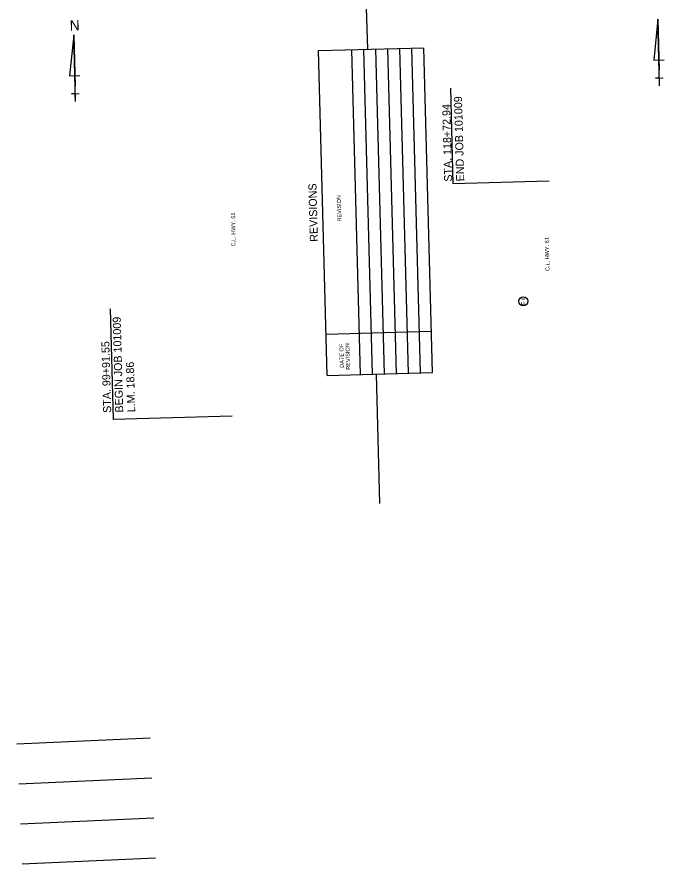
# Model space of a CAD drawing. Extents: x 1930579 to 1931599, y 596452 to 598574.
# Drawn here: x 1930579 to 1931549, y 596452 to 597722 of the extents above; entities that cross this region are included whole.
import ezdxf

# ---------------------------------------------------------------- set-up
doc = ezdxf.new("R2010")
doc.units = 0
for name, color, linetype in [('BR_Pr_Bent_CL', 7, 'Continuous'), ('Default', 7, 'Continuous'), ('R_Annotation', 7, 'Continuous'), ('R_Border', 7, 'Continuous'), ('R_Erosion', 7, 'Continuous'), ('S_BASELINE', 7, 'Continuous')]:
    doc.layers.add(name, color=color, linetype=linetype)

msp = doc.modelspace()

# ---------------------------------------------------------------- linework, layer by layer
at = {"layer": 'BR_Pr_Bent_CL'}
for p, q in [((1930779.3, 596640.3), (1930579.5, 596631.6)), ((1930781.9, 596580.4), (1930582.1, 596571.7)), ((1930784.5, 596520.4), (1930584.7, 596511.8)), ((1930787.1, 596460.5), (1930587.3, 596451.8))]:
    msp.add_line(p, q, dxfattribs=at)
at = {"layer": 'R_Annotation'}
for points in [[(1931377.2, 597475.2), (1931233.5, 597471.3), (1931229.7, 597615)], [(1930901.9, 597122.9), (1930724, 597118.1), (1930719.5, 597283.8)]]:
    msp.add_lwpolyline(points, dxfattribs=at)
at = {"layer": 'R_Border'}
for p, q in [((1931105.2, 597673), (1931088, 598314)), ((1931540.1, 597718.4), (1931534, 597656.6)), ((1931542.8, 597618.4), (1931540.1, 597718.4)), ((1931540.1, 597718.4), (1931542.1, 597641.5)), ((1930664.6, 597694.9), (1930658.5, 597633.1)), ((1930667.3, 597594.9), (1930664.6, 597694.9)), ((1930664.6, 597694.9), (1930666.6, 597618)), ((1931534, 597656.6), (1931549.4, 597657)), ((1931542.8, 597618.4), (1931542.1, 597641.5)), ((1930658.5, 597633.1), (1930673.9, 597633.5)), ((1931536.7, 597629.8), (1931548.2, 597630.1)), ((1931542.4, 597629.9), (1931536.7, 597629.8)), ((1931542.8, 597618.4), (1931542.4, 597629.9)), ((1930667.3, 597594.9), (1930666.6, 597618)), ((1930661.2, 597606.3), (1930672.7, 597606.6)), ((1930667, 597606.4), (1930661.2, 597606.3)), ((1930667.3, 597594.9), (1930667, 597606.4)), ((1931123.5, 596992.3), (1931118.2, 597186.3))]:
    msp.add_line(p, q, dxfattribs=at)
at = {"layer": 'R_Erosion'}
msp.add_circle((1931338.6, 597295.3), 6.88, dxfattribs=at)
at = {"layer": 'S_BASELINE'}
for p, q in [((1931031.4, 597671), (1931189.3, 597675.2)), ((1931112.4, 597186.2), (1931099.4, 597672.8)), ((1931130.4, 597186.7), (1931117.4, 597673.3)), ((1931148.4, 597187.1), (1931135.4, 597673.8)), ((1931166.4, 597187.6), (1931153.4, 597674.2)), ((1931184.4, 597188.1), (1931171.4, 597674.7)), ((1931202.4, 597188.6), (1931189.3, 597675.2)), ((1931044.5, 597184.3), (1931031.4, 597671)), ((1931094.5, 597185.7), (1931081.4, 597672.3)), ((1931042.8, 597246.1), (1931200.8, 597250.4)), ((1931044.5, 597184.3), (1931202.4, 597188.6))]:
    msp.add_line(p, q, dxfattribs=at)

# ---------------------------------------------------------------- texts
at = {"layer": 'Default'}
for s, p in [('END JOB 101009', (1931249.9, 597475.2)), ('STA. 118+72.94', (1931231.9, 597474.7)), ('BEGIN JOB 101009', (1930738.8, 597128.7)), ('STA. 99+91.55', (1930720.8, 597128.2)), ('L.M. 18.86', (1930756.8, 597129.1))]:
    msp.add_text(s, height=12, rotation=91.5377, dxfattribs=at).set_placement(p)
at = {"layer": 'R_Annotation'}
for rotation, p in [(90.2865, (1930906.8, 597377.6)), (91.2515, (1931377.7, 597340.8))]:
    msp.add_text('C,L. HWY. 61', height=6, rotation=rotation, dxfattribs=at).set_placement(p)
at = {"layer": 'R_Border'}
msp.add_text('N', height=15.4, rotation=1.5377, dxfattribs=at).set_placement((1930658.8, 597701.1))
at = {"layer": 'R_Erosion'}
msp.add_text('E-6 ', height=5, rotation=90, dxfattribs=at).set_placement((1931340.7, 597289.9))
at = {"layer": 'S_BASELINE'}
for s, height, p in [('REVISIONS', 12, (1931030.6, 597384.7)), ('REVISION', 6, (1931065.8, 597414.9)), ('DATE OF', 6, (1931069.5, 597195.7)), ('REVISION', 6, (1931078.9, 597192.9))]:
    msp.add_text(s, height=height, rotation=91.5377, dxfattribs=at).set_placement(p)

doc.saveas('drawing.dxf')
